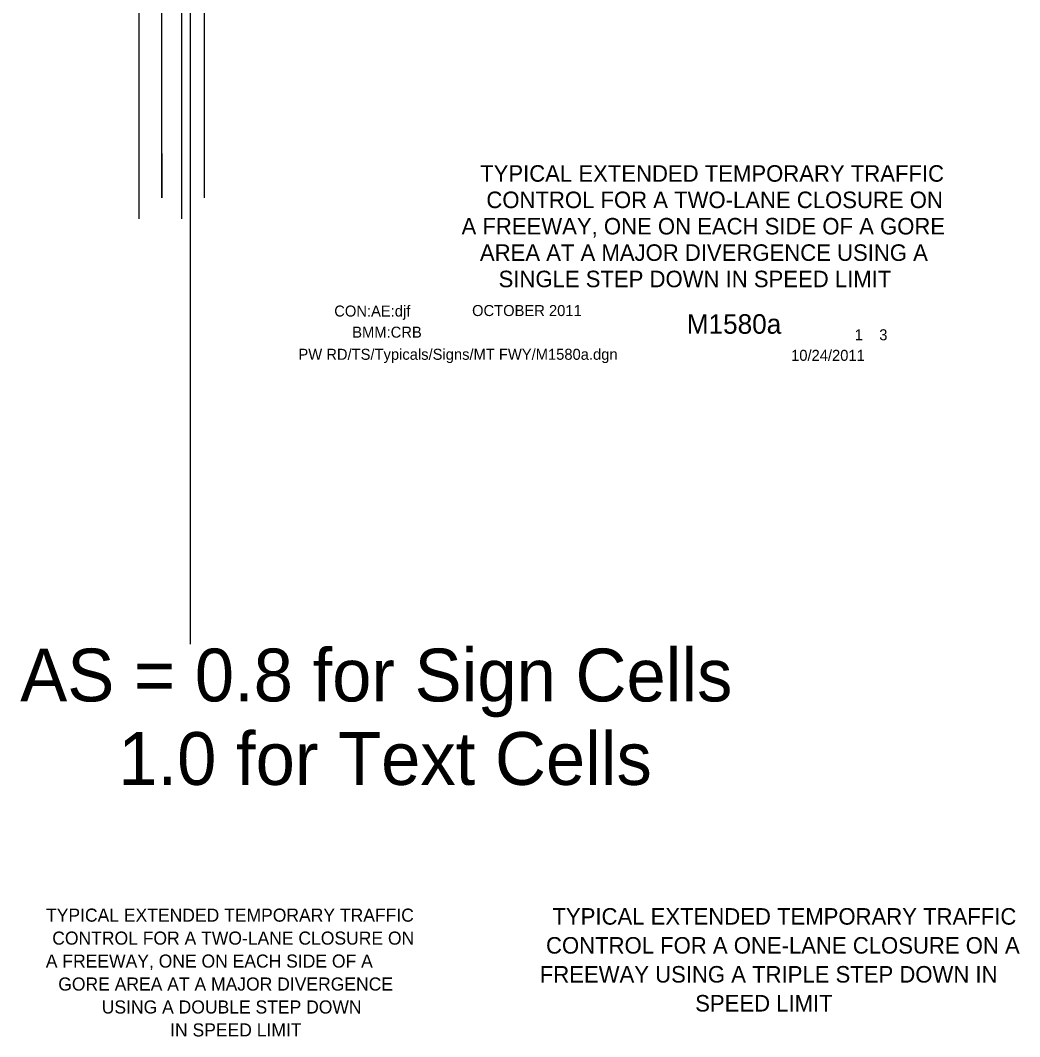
# Model space of a CAD drawing. Extents: x 16728 to 19508, y 5553 to 7079.
# Drawn here: x 16914 to 17477, y 5553 to 6125 of the extents above; entities that cross this region are included whole.
import ezdxf

# ---------------------------------------------------------------- set-up
doc = ezdxf.new("R2010")
doc.units = 0
for name, color, linetype in [('ALI_LEGAL_EX', 7, 'Continuous'), ('BORDER', 7, 'Continuous'), ('BORDER_SIGNAL_WO', 7, 'Continuous')]:
    doc.layers.add(name, color=color, linetype=linetype)

msp = doc.modelspace()

# ---------------------------------------------------------------- linework, layer by layer
at = {"layer": 'ALI_LEGAL_EX'}
for p, q in [((16980.68, 6877.04), (16980.68, 6013.12)), ((17004.68, 6877.04), (17004.68, 6013.12)), ((16993.65, 6024.8), (16993.65, 6525.15)), ((17017.65, 6024.8), (17017.65, 6525.15)), ((17009.75, 5773.57), (17009.75, 6383.76))]:
    msp.add_line(p, q, dxfattribs=at)
msp.add_lwpolyline([(16993.65, 6049.8), (16993.65, 6024.8)], dxfattribs=at)

# ---------------------------------------------------------------- texts
at = {"layer": 'BORDER'}
for s, height, p in [('TYPICAL EXTENDED TEMPORARY TRAFFIC', 9.3, (17172.85, 6033.97)), ('CONTROL FOR A TWO-LANE CLOSURE ON', 9.3, (17176.35, 6019.11)), ('A FREEWAY, ONE ON EACH SIDE OF A GORE', 9.3, (17162.37, 6004.27)), ('AREA AT A MAJOR DIVERGENCE USING A', 9.3, (17172.72, 5989.41)), ('SINGLE STEP DOWN IN SPEED LIMIT', 9.3, (17183.22, 5974.57)), ('TYPICAL EXTENDED TEMPORARY TRAFFIC', 7.3743, (16928.4, 5617.4)), ('TYPICAL EXTENDED TEMPORARY TRAFFIC', 9.3, (17213.56, 5615.73)), ('CONTROL FOR A TWO-LANE CLOSURE ON', 7.3743, (16931.9, 5604.47)), ('CONTROL FOR A ONE-LANE CLOSURE ON A', 9.3, (17209.93, 5599.43)), ('A FREEWAY, ONE ON EACH SIDE OF A  ', 7.3743, (16928.28, 5591.55)), ('FREEWAY USING A TRIPLE STEP DOWN IN ', 9.3, (17206.43, 5583.13)), ('GORE AREA AT A MAJOR DIVERGENCE ', 7.3743, (16935.28, 5578.62)), ('USING A DOUBLE STEP DOWN ', 7.3743, (16959.78, 5565.7)), ('SPEED LIMIT', 9.3, (17293.93, 5566.83)), ('IN SPEED LIMIT', 7.3743, (16998.28, 5552.78))]:
    msp.add_text(s, height=height, dxfattribs=at).set_placement(p)
at = {"layer": 'BORDER_SIGNAL_WO'}
for s, height, p in [('CON:AE:djf  ', 6.2, (17090.69, 5958.06)), ('    OCTOBER 2011    ', 6.2, (17159.08, 5958.34)), ('    M1580a   ', 11, (17272.86, 5948.38)), ('BMM:CRB   ', 6.2, (17100.81, 5946.17)), (' 1    3 ', 6.2, (17381.45, 5944.7)), ('PW RD/TS/Typicals/Signs/MT FWY/M1580a.dgn      ', 6.2, (17070.55, 5933.71)), ('10/24/2011    ', 6.2, (17347.93, 5933.13)), ('AS = 0.8 for Sign Cells', 29.7271, (16913.84, 5741.4)), ('     1.0 for Text Cells', 29.7271, (16913.84, 5694.4))]:
    msp.add_text(s, height=height, dxfattribs=at).set_placement(p)

doc.saveas('drawing.dxf')
